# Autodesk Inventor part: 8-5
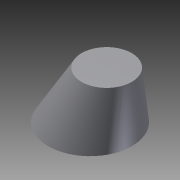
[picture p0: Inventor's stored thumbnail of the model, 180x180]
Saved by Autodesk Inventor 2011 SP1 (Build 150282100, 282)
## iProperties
Created: 2014-01
Part Number: 8-5
Document SubType Name: Modeling
Designer: Administrator
Density: 1 g/cm^3
Author: Administrator
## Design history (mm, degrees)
sketch "草图1"
  geometry: C1 r 15 at (0, 0); 1 further point
  constraints: 1 centre point, 1 coincident
  dimensions: "d0" = 30 diameter of C1
node "工作平面1"
sketch "草图2"
  geometry: C1 r 9 at (6, 0); 1 further point
  constraints: 1 centre point
  dimensions: "d2" = 18 diameter of C1; "d3" = 6 distance of C1.centre point (0, 0)
feature "放样1" sketch "草图2" dims "d4" = 0, "d5" = 90 deg, "d6" = 0, "d7" = 90 deg
node "实体1"
